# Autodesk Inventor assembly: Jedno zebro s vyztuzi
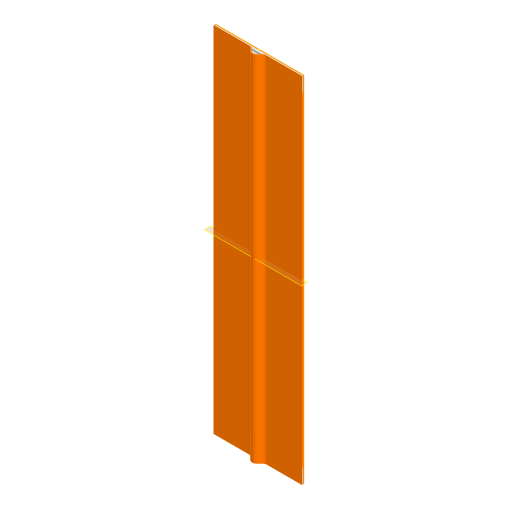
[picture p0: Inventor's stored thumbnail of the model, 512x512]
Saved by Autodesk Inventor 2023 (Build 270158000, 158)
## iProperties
Created: 2025-03
Part Number: Jedno zebro s vyztuzi
Document SubType Name: Assembly
Designer: tomik
Author: tomik
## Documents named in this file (4)
- C:\Users\tomik\Desktop\Růčka_Tomáš_přílohy\Vyztužení\Jedno žebro s kanálky\Jedno zebro_kanalek.iam
- C:\Users\tomik\Desktop\Růčka_Tomáš_přílohy\Vyztužení\Jedno žebro s kanálky\Zebro_kanalek.ipt
- C:\Users\tomik\Desktop\Růčka_Tomáš_přílohy\Vyztužení\Jedno žebro s kanálky\Spodni tkanina 50x200.ipt
- C:\Users\tomik\Desktop\Růčka_Tomáš_přílohy\Vyztužení\Jedno žebro s kanálky\Horni tkanina.ipt
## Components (3 placed, 3 different names)
1. Zebro_kanalek:1 — Proti sobě:1, Proti sobě:2, Stejný směr:1, Proti sobě:6, Stejný směr:2, Proti sobě:7
2. Spodni tkanina 50x200:1 — Proti sobě:6, Stejný směr:2, Proti sobě:7, Proti sobě:8, Stejný směr:3, Stejný směr:4
3. Horni tkanina:1 — Proti sobě:8, Stejný směr:3, Stejný směr:4
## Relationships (9: Mate 5, Flush 4)
- Proti sobě:1 [Mate]: Zebro_kanalek:1
- Proti sobě:2 [Mate]: Zebro_kanalek:1
- Stejný směr:1 [Flush]: Zebro_kanalek:1
- Proti sobě:6 [Mate]: Zebro_kanalek:1 ↔ Spodni tkanina 50x200:1
- Stejný směr:2 [Flush]: Zebro_kanalek:1 ↔ Spodni tkanina 50x200:1
- Proti sobě:7 [Mate]: Zebro_kanalek:1 ↔ Spodni tkanina 50x200:1
- Proti sobě:8 [Mate]: Spodni tkanina 50x200:1 ↔ Horni tkanina:1
- Stejný směr:3 [Flush]: Spodni tkanina 50x200:1 ↔ Horni tkanina:1
- Stejný směr:4 [Flush]: Spodni tkanina 50x200:1 ↔ Horni tkanina:1
